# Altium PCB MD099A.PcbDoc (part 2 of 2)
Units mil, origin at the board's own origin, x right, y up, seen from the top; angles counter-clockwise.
Board outline 4255 x 2850 mil, 4 copper layers (Top Layer, Ground, Power, Bottom Layer), stack 61.6 mil thick; 151 components, 81 nets, 392 pads, 633 vias.
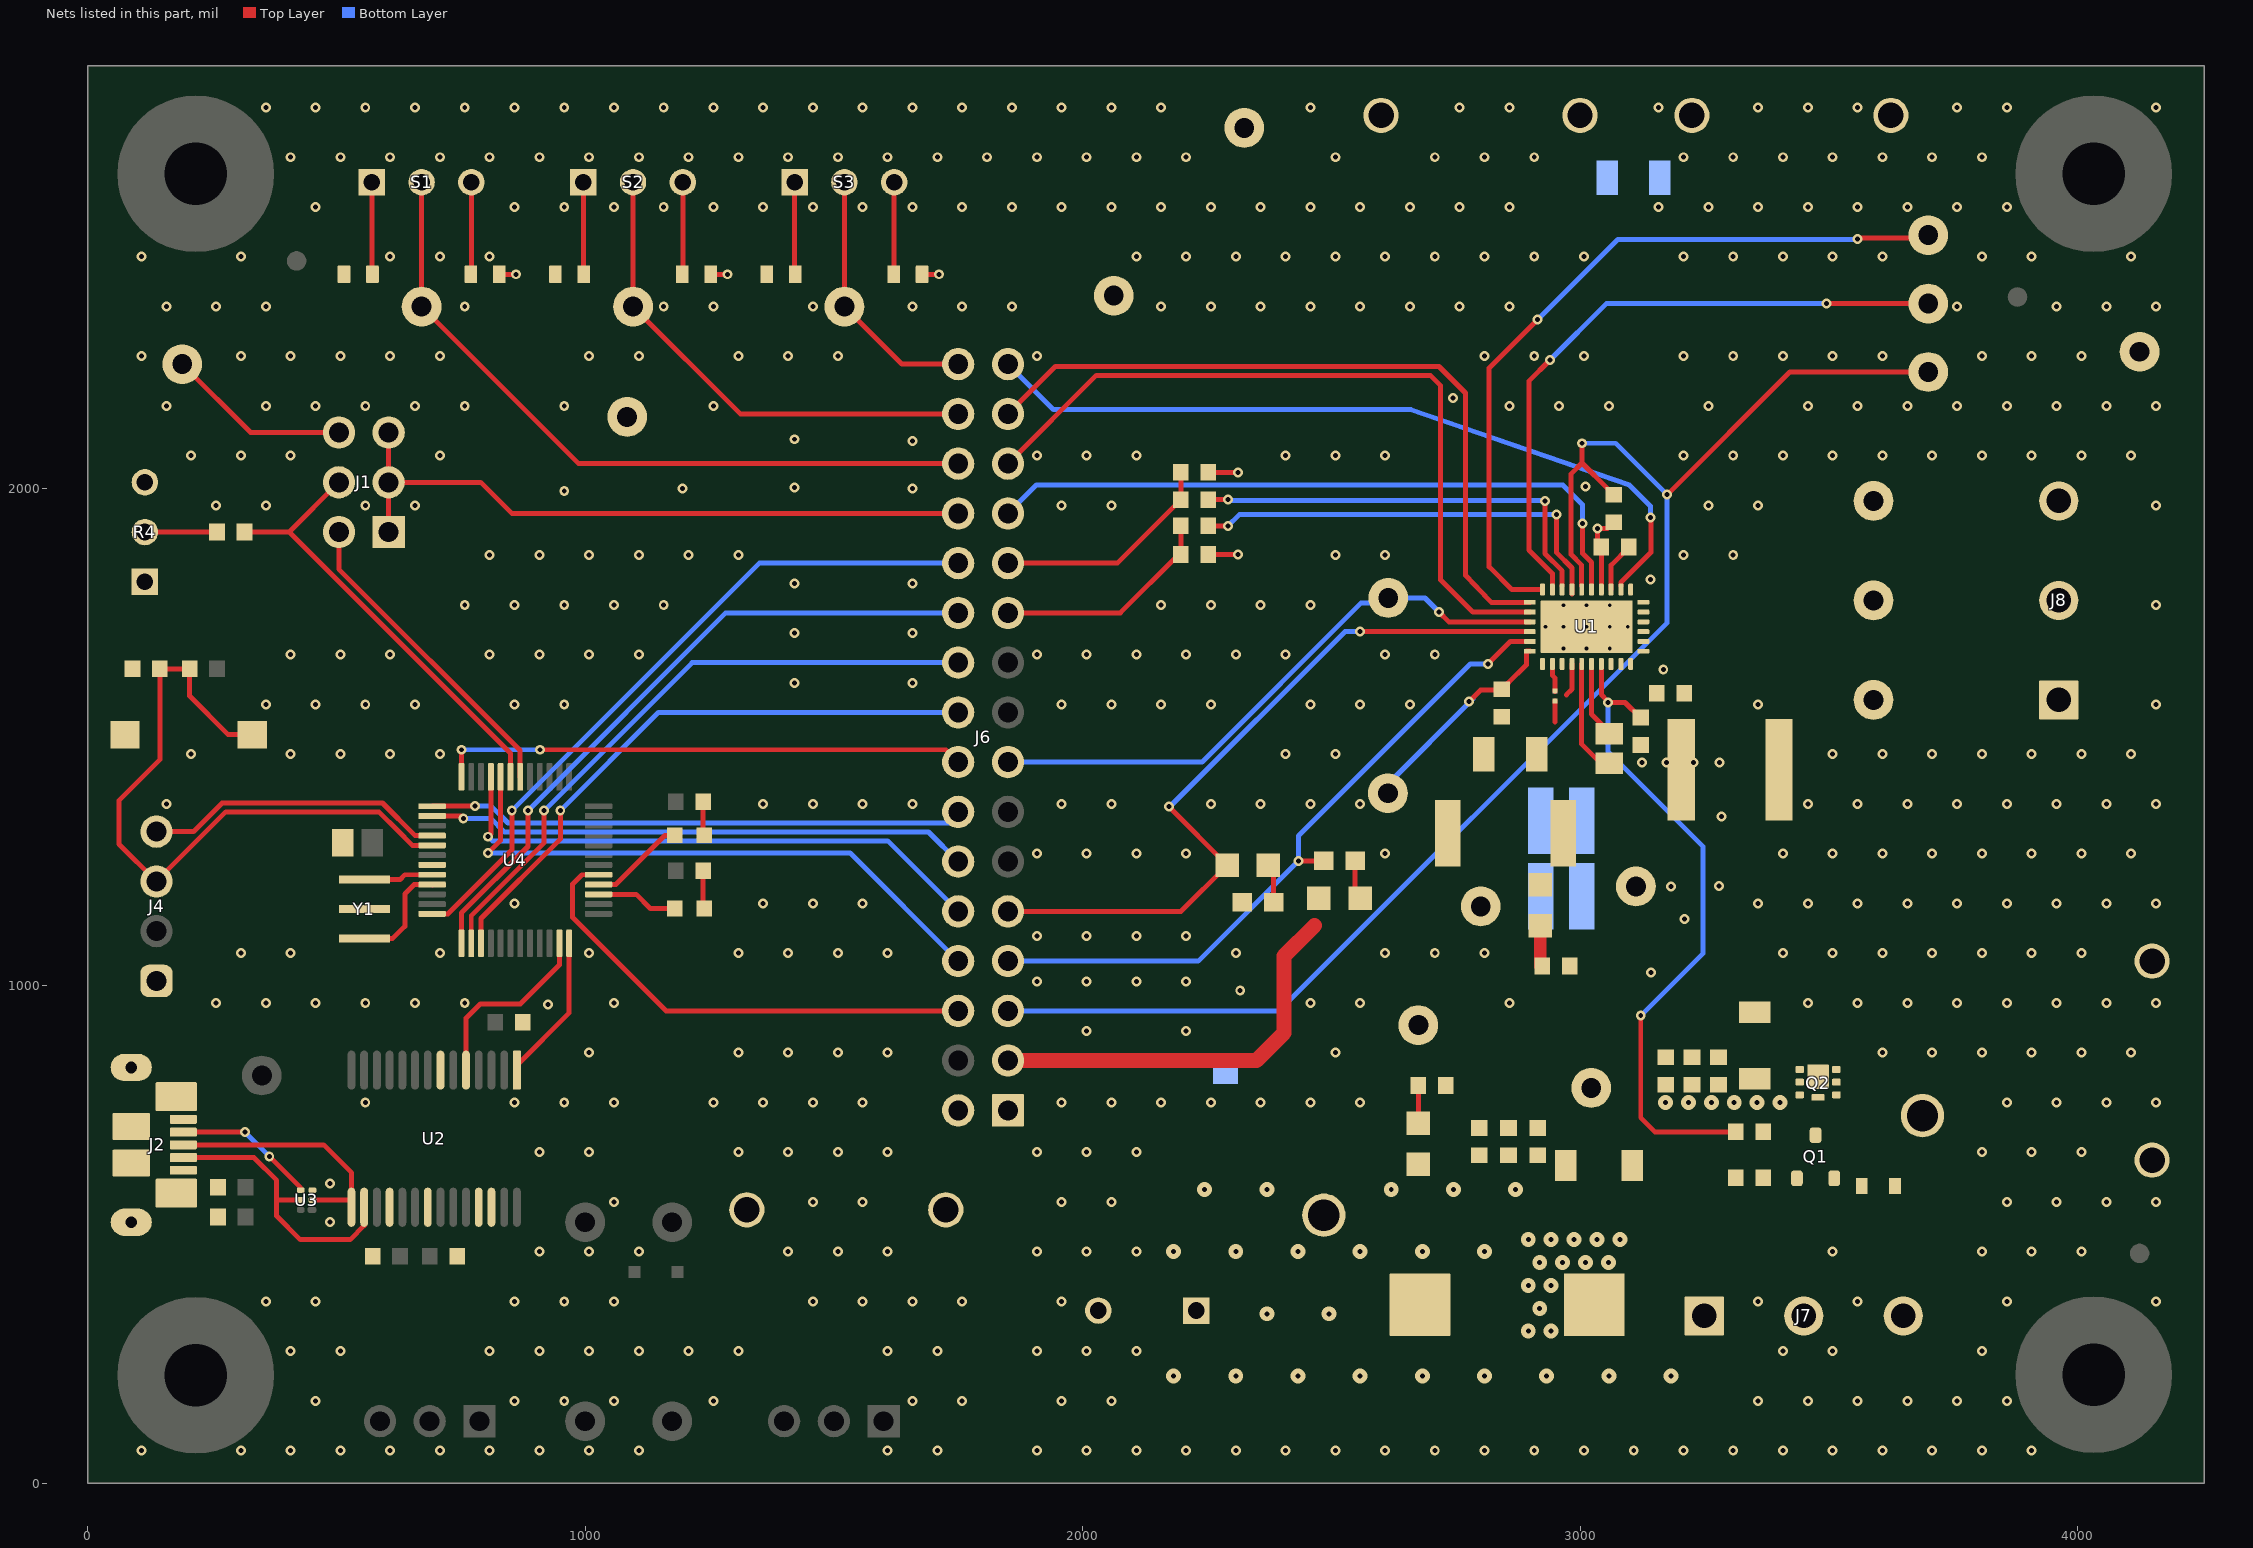
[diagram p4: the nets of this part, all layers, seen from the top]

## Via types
v1: diameter 20, hole 10, Top Layer to Bottom Layer, tented both sides, 580 vias
v2: diameter 30, hole 10, Top Layer to Bottom Layer, tented both sides, 42 vias
v3: diameter 19.68, hole 7.87, Top Layer to Bottom Layer, tented both sides, 11 vias

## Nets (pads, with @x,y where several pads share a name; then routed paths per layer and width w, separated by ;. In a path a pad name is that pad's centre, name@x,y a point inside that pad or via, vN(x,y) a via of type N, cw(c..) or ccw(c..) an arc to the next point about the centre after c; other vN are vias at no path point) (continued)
AGND: C4.1 C5.1 C7.2 C8.2 C9.2 C10.1 C11.2 C12.2 C13.2 J2.5 J2.6 J2.7 J2.8 J2.9 J2.10 J2.11 J4.1 J6.1 J6.2 NT2.1 R4.3 R6.1 R7.1 R8.1 R15.1 R17.1 R24.1 S4.2 TP24.1 TP24.2 TP25.1 TP25.2 TP28.1 TP29.1 TP30.1 U1.1 U1.3 U1.19 U1.33 U2.7 U2.18 U2.21 U2.25 U2.26 U3.3 U4.7 Y1.2 | length 100.3
  Top Layer w10: U1.19@3062.5,1796.91 3062.5,1846.08 3097.93,1881.52 C4.1@3097.93,1882.5
  other v1: 108,66 308,66 408,66 508,66 608,66 708,66 808,66 908,66 1008,66 1108,66 1608,66 1708,66 458,166 858,166 958,166 1058,166 1258,166 1658,166 1758,166 408,266 508,266 808,266 908,266 1008,266 1108,266 1208,266 1308,266 1608,266 1708,266 358,366 458,366 858,366 958,366 1058,366 1458,366 1558,366 1658,366 1758,366 908,466 1008,466 1108,466 1408,466 1508,466 1608,466 487.5,525.08 1058,566 1458,566 1558,566 487.5,602.5 908,666 1008,666 1308,666 1408,666 1508,666 1608,666 558,766 858,766 958,766 1058,766 1258,766 1358,766 1458,766 1558,766 1008,866 1308,866 1408,866 1508,866 1608,866 2508,866 2008,909.3 2208,909.3 925,962.5 258,966 358,966 458,966 558,966 658,966 758,966 1058,966 2458,966 2558,966 2858,966 2316.93,990.7 1908,1009.3 2008,1009.3 2108,1009.3 2208,1009.3 308,1066 408,1066 708,1066 1008,1066 1308,1066 1408,1066 1508,1066 1608,1066 2308,1066 2608,1066 2708,1066 2808,1066 1908,1100 2008,1100 2108,1100 2208,1100 858,1166 1358,1166 1458,1166 1558,1166 1908,1266 2008,1266 2108,1266 2208,1266 2608,1266 158,1366 1358,1366 1458,1366 1558,1366 1658,1366 1958,1366 2058,1366 2258,1366 2358,1366 2458,1366 2558,1366 208,1466 408,1466 508,1466 608,1466 708,1466 2408,1466 2508,1466 358,1566 458,1566 558,1566 658,1566 858,1566 958,1566 1958,1566 2058,1566 2158,1566 2258,1566 2458,1566 2558,1566 2658,1566 1421.27,1609.3 1658,1609.3 408,1666 508,1666 608,1666 808,1666 908,1666 1008,1666 1108,1666 1908,1666 2008,1666 2108,1666 2208,1666 2308,1666 2408,1666 2608,1666 2708,1666 1421.27,1709.3 1658,1709.3 758,1766 858,1766 958,1766 1058,1766 1158,1766 2158,1766 2258,1766 2358,1766 2458,1766 1421.27,1809.3 1658,1809.3 808,1866 908,1866 1008,1866 1108,1866 1208,1866 1308,1866 2508,1866 2608,1866 258,1966 358,1966 558,1966 658,1966 1958,1966 2058,1966 958,1995 1195.29,1999.89 1658,1999.89 1421.27,2002.11 3010.81,2004.4 208,2066 308,2066 408,2066 708,2066 1908,2066 2008,2066 2108,2066 2408,2066 2508,2066 2608,2066 1658,2095.09 1421.27,2099.06 158,2166 358,2166 458,2166 558,2166 658,2166 758,2166 958,2166 1258,2166 2858,2166 2958,2166 3058,2166 2745,2181.65 108,2266 308,2266 408,2266 508,2266 608,2266 708,2266 1008,2266 1108,2266 1308,2266 1408,2266 1508,2266 1908,2266 2808,2266 2908,2266 3008,2266 158,2366 258,2366 358,2366 758,2366 1158,2366 1258,2366 1458,2366 1658,2366 1758,2366 1858,2366 2158,2366 2258,2366 2358,2366 2458,2366 2558,2366 2658,2366 2758,2366 2858,2366 108,2466 308,2466 608,2466 708,2466 808,2466 2108,2466 2208,2466 2308,2466 2408,2466 2508,2466 2608,2466 2708,2466 2808,2466 2908,2466 3008,2466 458,2566 858,2566 958,2566 1058,2566 1158,2566 1258,2566 1358,2566 1458,2566 1558,2566 1658,2566 1758,2566 1858,2566 1958,2566 2058,2566 2158,2566 2258,2566 2358,2566 2458,2566 2558,2566 2658,2566 2758,2566 2858,2566 408,2666 508,2666 608,2666 708,2666 808,2666 908,2666 1008,2666 1108,2666 1208,2666 1308,2666 1408,2666 1508,2666 1608,2666 1708,2666 1808,2666 1908,2666 2008,2666 2108,2666 2208,2666 2508,2666 2708,2666 2808,2666 2908,2666 358,2766 458,2766 558,2766 658,2766 758,2766 858,2766 958,2766 1058,2766 1158,2766 1258,2766 1358,2766 1458,2766 1558,2766 1658,2766 1758,2766 1858,2766 1958,2766 2058,2766 2158,2766 2458,2766 2758,2766 2858,2766
  other v3: 2966.83,1678.8 3013.29,1678.8 3059.74,1678.8 2930.61,1722.11 2966.83,1722.11 3013.29,1722.11 3059.74,1722.11 3095.96,1722.11 2966.83,1765.41 3013.29,1765.41 3059.74,1765.41
ALARM: D3.1 J6.9 U1.30 | length 1509.6
  Top Layer w10: J6.9@1850,1150 2197.82,1150 D3.1@2290.82,1243 2173.82,1360 v1(2173.82,1360.66) ; v1(2558,1712.29) U1.30@2892.3,1712.28
  Bottom Layer w10: v1(2173.82,1360.66) 2175.87,1360.66 2527.5,1712.29 v1(2558,1712.29)
AVDD: C4.2 R1.2 R2.2 R3.2 R4.1 R9.2 R10.1 R11.1 TP5.1 U1.20 | length 355.8
  Top Layer w10: R1.2@826.33,2430.7 v1(861.27,2430.7) ; R2.2@1251.33,2430.7 v1(1286.27,2430.7) ; R3.2@1676.33,2430.7 v1(1711.27,2430.7) ; R11.1@2256.5,1867.5 v1(2312.5,1867.5) ; R10.1@2256.5,2032.5 v1(2312.5,2032.5) ; C4.2@3035,1882.5 v1(3035,1920) 3055.06,1920 R9.2@3067.5,1932.44 ; U1.20@3042.74,1803.72 C4.2@3042.82,1867.53
BRAKE: J6.27 U1.28 | length 1548.5
  Top Layer w10: J6.27@1850,2050 2027.5,2227.5 2699.22,2227.5 2720,2206.72 2720,1816.14 2784.51,1751.63 U1.28@2899.11,1751.63
BRAKE_SW: J6.28 S1.2 TP1.1 | length 1459.5
  Top Layer w10: S1.2@671.27,2615.7 TP1.1@671.27,2365.7 986.97,2050 J6.28@1750,2050
CPH: C6.1 U1.6 | length 149
  Top Layer w10: U1.6@3023.13,1647.3 3023.13,1546.55 3052.64,1517.04 C6.1@3059.14,1517.04
CPL: C6.2 U1.5 | length 243.6
  Top Layer w10: U1.5@3003.44,1647.3 3003.44,1486.23 3052.64,1437.04 C6.2@3059.14,1437.04 ; C6.2@3046.75,1454.47 C6.2@3053.25,1454.47
DACOUT: J6.15 TP12.1 U1.29 | length 1205.7
  Top Layer w10: v1(2716.63,1751.63) 2736.31,1731.95 U1.29@2899.11,1731.95
  Bottom Layer w10: J6.15@1850,1450 2239.93,1450 2559.5,1769.57 2604.07,1769.57 TP12.1@2614.5,1780 2688.26,1780 v1(2716.63,1751.63)
DIR: J6.29 U1.27 | length 1500.5
  Top Layer w10: J6.29@1850,2150 1945.37,2245.37 2716.63,2245.37 2769.89,2192.11 2769.89,1825.62 2818.55,1774.34 2818.64,1774.25 2821.57,1771.32 U1.27@2899.11,1771.32
DIR_SW: J6.30 S2.2 TP2.1 | length 993.1
  Top Layer w10: S2.2@1096.27,2615.7 TP2.1@1096.27,2365.7 1311.97,2150 J6.30@1750,2150
DM: J2.2 U2.16 U3.5 | length 585.4
  Top Layer w10: J2.2@192.22,655 334.14,655 380,609.14 380,570 ; U3.5@428.19,569.59 380.41,569.59 380,570 ; U2.16@556.23,569.59 556.23,518.73 527.5,490 427.5,490 380,537.5 380,570
DP: J2.3 U2.15 U3.2 | length 495.3
  Top Layer w10: J2.3@192.22,680.59 474.41,680.59 530.64,624.36 530.64,569.59 U3.2@451.81,569.59
DRVOFF: J6.31 U1.18 | length 1558.7
  Top Layer w10: U1.18@3082.18,1803.72 3082.18,1811.01 3142.5,1871.33 3142.5,1941.06 v1(3141.37,1942.19)
  Bottom Layer w10: J6.31@1850,2250 1938.51,2161.49 1941.44,2158.56 2658.47,2158.56 2660.14,2158.56 3099.26,2006.92 3141.37,1964.81 v1(3141.37,1942.19)
DRVOFF_SW: J6.32 S3.2 TP3.1 | length 526.7
  Top Layer w10: S3.2@1521.27,2615.7 TP3.1@1521.27,2365.7 1636.97,2250 J6.32@1750,2250
DVDD: C5.2 TP6.1 U1.32 | length 440.2
  Top Layer w10: v1(2777.26,1571.69) 2800.1,1594.53 2841.25,1594.53 2841.25,1595.51 2854.95,1609.22 2855.93,1609.22 2892.04,1645.32 2892.04,1665.82 2892.3,1666.08 2892.3,1672.82 2892.38,1672.89 U1.32@2899.11,1672.89
  Bottom Layer w10: TP6.1@2613.86,1387.5 2613.86,1406.1 v1@2784.51,1576.75
EXT_CLK: TP11.1 U1.26 | length 1518.9
  Top Layer w10: v1(2914.66,2339.39) 2817.5,2242.23 2817.5,1842.5 2863.09,1796.91 U1.26@2924.7,1796.91 ; v1(3558,2501.32) 3560.68,2504 3694.75,2504 TP11.1@3700,2509.25
  Bottom Layer w10: v1(2914.66,2339.39) 3076.3,2501.03 3557.71,2501.03 v1(3558,2501.32)
EXT_WD: TP10.1 U1.25 | length 1299.1
  Top Layer w10: v1(2939.66,2258.4) 2897.16,2215.9 2897.16,1876.36 2944.39,1829.13 U1.25@2944.39,1803.72 ; v1(3495.5,2371.75) TP10.1@3700,2371.75
  Bottom Layer w10: v1(2939.66,2258.4) 3053.01,2371.75 v1(3495.5,2371.75)
FB_BUCK: NT1.1 U1.2 | length 57.5
  Top Layer w10: U1.2@2944.39,1647.3 2944.27,1624.41 2949.38,1619.3 NT1.1@2949.39,1591.93
FG: J6.5 R9.1 TP13.1 U1.22 | length 3142.6
  Top Layer w10: 2982.13,1920.52 2982.13,1867.22 3003.44,1845.91 U1.22@3003.44,1803.72 ; 2982.13,1920.53 2982.13,2029.51 3003.84,2051.22 ; v1(3003.84,2091) 3003.84,2051.22 ; R9.1@3067.5,1987.56 3066.52,1987.56 3055.77,1998.31 3055.77,1999.29 3003.84,2051.22 ; v1(3175.06,1987.56) 3421.75,2234.25 TP13.1@3700,2234.25
  Bottom Layer w10: J6.5@1850,950 2395,950 3175.06,1730.06 v1(3175.06,1987.56) 3071.62,2091 v1(3003.84,2091)
ID: J2.4 U3.4 | length 287.3
  Top Layer w10: J2.4@192.22,706.18 v1(316.27,706.18) ; v1(365,657.5) 428.19,594.31 U3.4@428.19,589.28
  Bottom Layer w10: v1(316.27,706.18) 364.95,657.5 v1(365,657.5)
MCX_SCL: J6.23 R10.2 R12.1 | length 456.9
  Top Layer w10: J6.23@1850,1850 2069.94,1850 R12.1@2197.44,1977.5 2197.44,2028.56 R10.2@2193.5,2032.5
MCX_SDA: J6.21 R11.2 R13.1 | length 451.3
  Top Layer w10: J6.21@1850,1750 2076,1750 2193.5,1867.5 2197.44,1871.44 R13.1@2197.44,1925
MSP_A1_P1.1: J6.12 U4.2 | length 1094.7
  Top Layer w10: U4.2@693.3,1341.67 750.24,1341.67 v1(755,1336.91)
  Bottom Layer w10: v1(755,1336.91) 810.31,1336.91 837.6,1309.63 1690.37,1309.63 J6.12@1750,1250
MSP_A2_P1.2: J6.14 U4.1 | length 1070.7
  Top Layer w10: U4.1@693.3,1361.36 v1(778.64,1361.36)
  Bottom Layer w10: v1(778.64,1361.36) 811.14,1361.36 845,1327.5 J6.14@1750,1327.5
MSP_A3_P1.3: J6.16 U4.48 | length 1063.4
  Top Layer w10: U4.48@751.37,1420.41 v1(751.37,1474.85) ; v1(909.45,1474.85) 1725.15,1474.85 J6.16@1750,1450
  Bottom Layer w10: v1(751.37,1474.85) v1(909.45,1474.85)
MSP_ALARM_P3.2: J6.10 U4.45 | length 1130.1
  Top Layer w10: v1(805,1300) 810.43,1305.43 810.43,1419.43 U4.45@811.33,1420.33
  Bottom Layer w10: v1(805,1300) 813.25,1291.75 1608.25,1291.75 J6.10@1750,1150
MSP_CLK_P4.5: J6.20 U4.14 | length 1282.1
  Top Layer w10: U4.14@771.06,1086.75 771.06,1141.3 917.5,1287.74 v1(917.5,1352.5)
  Bottom Layer w10: v1(917.5,1352.5) 1215,1650 J6.20@1750,1650
MSP_FG_P2.1: J6.6 U4.29 | length 978.8
  Top Layer w10: U4.29@1025.98,1223.56 993.56,1223.56 975,1205 975,1137.5 1162.5,950 J6.6@1750,950
MSP_LED0_P2.2: D6.2 U4.28 | length 195.1
  Top Layer w10: U4.28@1025.98,1203.88 1061.68,1203.88 1160.49,1302.7 D6.2@1180.11,1302.7
MSP_LED1_P2.3: D7.2 U4.27 | length 166
  Top Layer w10: U4.27@1025.98,1184.19 1102.5,1184.19 1131.1,1155.59 D7.2@1180.11,1155.59
MSP_nFAULT_P3.3: J6.8 U4.44 | length 1197.4
  Top Layer w10: v1(805,1267.5) 829.63,1292.13 829.63,1418.94 U4.44@830.11,1419.43
  Bottom Layer w10: v1(805,1267.5) 1532.5,1267.5 J6.8@1750,1050
MSP_PWM: J1.2 U4.42 | length 643.1
  Top Layer w10: J1.2@505.01,1912.5 505.01,1837.78 869.48,1473.31 U4.42@869.48,1420.41
MSP_RX_P4.3: U2.5 U4.23 | length 370.2
  Top Layer w10: U2.5@760.96,841.24 760.96,935.49 789.25,963.78 869.75,963.78 948.22,1042.25 U4.23@948.22,1086.75
MSP_SBWTCK: J4.4 U4.4 | length 617.6
  Top Layer w10: J4.4@145.74,1302.3 137.86,1310.18 212.58,1310.18 270.27,1367.87 592.8,1367.87 658.37,1302.3 U4.4@693.3,1302.3
MSP_SBWTDIO/nRST: C12.1 J4.3 R19.1 S4.1 U4.5 | length 1406.7
  Top Layer w10: S4.1@330.96,1505.27 282.5,1505.27 204.94,1582.83 R19.1@204.94,1637.5 C12.1@145.06,1637.5 145.06,1455 62.5,1372.44 62.5,1285.54 137.86,1210.18 277.68,1350 585.35,1350 624.97,1310.37 ; 625.02,1310.37 650.41,1284.98 ; 650.41,1284.94 652.73,1282.62 U4.5@693.3,1282.62
MSP_SCL_P4.7: J6.24 U4.12 | length 1396.5
  Top Layer w10: U4.12@694.21,1145.73 693.3,1144.82 724.03,1144.82 852.5,1273.3 v1(852.5,1352.5)
  Bottom Layer w10: v1(852.5,1352.5) 1350,1850 J6.24@1750,1850
MSP_SDA_P4.6: J6.22 U4.13 | length 1350.7
  Top Layer w10: U4.13@751.37,1086.75 751.37,1146.89 885,1280.52 v1(885,1352.5)
  Bottom Layer w10: v1(885,1352.5) 1282.5,1750 J6.22@1750,1750
MSP_STE_P4.4: J6.18 U4.15 | length 1213.5
  Top Layer w10: U4.15@790.74,1086.75 790.74,1135.71 950,1294.96 v1(950,1352.5)
  Bottom Layer w10: v1(950,1352.5) 1147.5,1550 J6.18@1750,1550
MSP_TX_P4.2: U2.1 U4.24 | length 288.8
  Top Layer w10: U2.1@863.32,841.24 967.91,945.83 U4.24@967.91,1086.75
MSP_XIN_P2.7: U4.8 Y1.1 | length 141.2
  Top Layer w10: Y1.1@556.22,1213.72 627.85,1213.72 637.69,1223.56 U4.8@693.3,1223.56
MSP_XOUT_P2.6: U4.9 Y1.3 | length 221.8
  Top Layer w10: Y1.3@556.83,1095 Y1.3@556.22,1095.61 613.11,1095.61 637.5,1120 637.5,1185 656.38,1203.88 693.3,1203.88 U4.9@693.3,1202.97
NetC15_1: C15.1 C16.1 C17.1 C18.1 L4.1 Q2.1 Q2.2 Q2.5 Q2.6 Q2.7
  other v2: 2896,306 2942,306 2919,352 2896,398 2942,398 2919,444 2965,444 3011,444 3057,444 2896,490 2942,490 2988,490 3034,490 3080,490 3172,766 3218,766 3264,766 3310,766 3356,766 3402,766
NetD1_2: D1.2 R15.2 | length 81.2
  Top Layer w25: R15.2@2920,1040 D1.2@2920,1121.16
NetD2_2: D2.2 R16.2 | length 79.1
  Top Layer w10: R16.2@2548,1251.5 2548,1186.34 D2.2@2557.84,1176.5
NetD3_2: D3.2 R17.2 | length 79.3
  Top Layer w10: D3.2@2373.5,1243 2384,1232.5 R17.2@2384,1168
NetD4_2: D4.2 R18.2 | length 76.2
  Top Layer w10: D4.2@2675,723.84 R18.2@2675,800
NetD6_1: D6.1 R20.1 | length 68.3
  Top Layer w10: R20.1@1237.2,1370.2 1237.2,1304.67 D6.1@1239.17,1302.7
NetD7_1: D7.1 R21.1 | length 76.7
  Top Layer w10: R21.1@1237.2,1231.43 1237.2,1157.56 D7.1@1239.17,1155.59
NetD8_2: D8.2 Q1.2
NetJ1_6: J1.6 TP4.1 | length 372
  Top Layer w10: TP4.1@190,2250 327.5,2112.5 J1.6@505.01,2112.5
NetJ2_1: J2.1 L3.2
NetQ1_1: Q1.1 R23.1
NetQ1_3: Q1.3 Q2.3 R22.2
NetR1_1: R1.1 S1.3 | length 185
  Top Layer w10: R1.1@771.27,2430.7 S1.3@771.27,2615.7
NetR2_1: R2.1 S2.3 | length 185
  Top Layer w10: R2.1@1196.27,2430.7 S2.3@1196.27,2615.7
NetR3_1: R3.1 S3.3 | length 185
  Top Layer w10: R3.1@1621.27,2430.7 S3.3@1621.27,2615.7
NetR4_2: R4.2 R5.2 | length 144.9
  Top Layer w10: R4.2@115,1912.5 R5.2@259.94,1912.5
NetR6_2: R6.2 S1.1 | length 185
  Top Layer w10: S1.1@571.27,2615.7 571.27,2430.76 R6.2@571.33,2430.7
NetR7_2: R7.2 S2.1 | length 185
  Top Layer w10: R7.2@996.27,2430.7 S2.1@996.27,2615.7
NetR8_2: R8.2 S3.1 | length 185
  Top Layer w10: R8.2@1421.27,2430.7 S3.1@1421.27,2615.7
nFAULT: J6.7 R16.1 U1.31 | length 1395.8
  Top Layer w10: v1(2434,1251.5) R16.1@2485,1251.5 ; v1(2814.68,1647.3) 2859.96,1692.58 U1.31@2899.11,1692.58
  Bottom Layer w10: J6.7@1850,1050 2232.5,1050 v1(2434,1251.5) 2434,1301.88 2779.43,1647.3 v1(2814.68,1647.3)
OUTA: J8.1 TP7.1 U1.11 U1.12
OUTB: J8.2 TP8.1 U1.13 U1.14
OUTC: J8.3 TP9.1 U1.15 U1.16
PGND: C2.2 C3.2 C14.2 C15.2 C16.2 C17.2 C18.2 C19.2 C20.2 C21.2 C22.2 J7.2 NT2.2 R18.1 R23.2 R24.2 TP23.1 TP26.1 TP26.2 TP27.1 TP27.2 TP31.1 U1.10 U1.17
  other v1: 1908,66 2008,66 2108,66 2208,66 2308,66 2408,66 2508,66 2608,66 2708,66 2808,66 2908,66 3008,66 3108,66 3208,66 3308,66 3408,66 3508,66 3608,66 3708,66 3808,66 3908,66 1958,166 2058,166 3358,166 3458,166 3558,166 3658,166 3758,166 3858,166 1908,266 2008,266 2108,266 3408,266 3508,266 3808,266 1958,366 3358,366 3558,366 3858,366 4158,366 1908,466 2008,466 2108,466 3508,466 3808,466 3908,466 4008,466 1958,566 2058,566 3858,566 3958,566 4058,566 4158,566 1908,666 2008,666 2108,666 3808,666 3908,666 4008,666 1958,766 2058,766 2158,766 2258,766 2358,766 2458,766 2558,766 3858,766 3958,766 4058,766 4158,766 3608,866 3708,866 3808,866 3908,866 4008,866 4108,866 3458,966 3558,966 3658,966 3758,966 3858,966 3958,966 4058,966 4158,966 3142.5,1027.5 3408,1066 3508,1066 3608,1066 3708,1066 3808,1066 3908,1066 4008,1066 3210,1135 3358,1166 3458,1166 3558,1166 3658,1166 3758,1166 3858,1166 3958,1166 4058,1166 4158,1166 3408,1266 3508,1266 3608,1266 3708,1266 3808,1266 3908,1266 4008,1266 4108,1266 3458,1366 3558,1366 3658,1366 3758,1366 3858,1366 3958,1366 4058,1366 4158,1366 3508,1466 3608,1466 3708,1466 3808,1466 3908,1466 4008,1466 4108,1466 3358,1566 4158,1566 3167.36,1636.1 4158,1766 3141.37,1816.82 3208,1866 3308,1866 3258,1966 3358,1966 4158,1966 3208,2066 3308,2066 3408,2066 3508,2066 3608,2066 3708,2066 3808,2066 3908,2066 4008,2066 4108,2066 3258,2166 3458,2166 3558,2166 3658,2166 3758,2166 3858,2166 3958,2166 4058,2166 4158,2166 3208,2266 3308,2266 3408,2266 3508,2266 3608,2266 3808,2266 3908,2266 4008,2266 3758,2366 3958,2366 4058,2366 4158,2366 3208,2466 3308,2466 3408,2466 3508,2466 3608,2466 3808,2466 3908,2466 4108,2466 3158,2566 3258,2566 3358,2566 3458,2566 3558,2566 3658,2566 3758,2566 3858,2566 3208,2666 3308,2666 3408,2666 3508,2666 3608,2666 3708,2666 3808,2666 3158,2766 3358,2766 3458,2766 3558,2766 3758,2766 3858,2766 4158,2766
POT: J1.4 R5.1 U4.43 | length 907.7
  Top Layer w10: R5.1@315.06,1912.5 405.01,1912.5 ; J1.4@505.01,2012.5 405.01,1912.5 ; U4.43@849.8,1420.41 849.8,1467.71 405.01,1912.5
SCL: R12.2 U1.24 | length 863.7
  Top Layer w10: R12.2@2252.56,1977.5 v1(2292.5,1977.5) ; v1(2929.63,1975) 2929.63,1869.17 2964.07,1834.72 U1.24@2964.07,1803.72
  Bottom Layer w10: v1(2292.5,1977.5) 2293.75,1976.25 2928.38,1976.25 v1(2929.63,1975)
SDA: R13.2 U1.23 | length 881.6
  Top Layer w10: R13.2@2252.56,1925 v1(2292.5,1925) ; v1(2952.5,1947.5) 2952.5,1871.57 2983.76,1840.31 U1.23@2983.76,1788.13
  Bottom Layer w10: v1(2292.5,1925) 2315,1947.5 v1(2952.5,1947.5)
SPEED: J6.25 U1.21 | length 1366.3
  Top Layer w10: v1(3005,1930) 3005,1869.63 3023.05,1851.58 U1.21@3023.05,1803.72
  Bottom Layer w10: J6.25@1850,1950 1907.09,2007.09 2965.41,2007.09 3005,1967.5 v1(3005,1930)
SPEED_IN: J1.1 J1.3 J1.5 J6.26 | length 1370.9
  Top Layer w10: J1.1@605.01,1912.5 J1.3@605.01,2012.5 ; J1.5@605.01,2112.5 J1.3@605.01,2012.5 ; J6.26@1750,1950 852.5,1950 790,2012.5 J1.3@605.01,2012.5
SW_BUCK: L1.1 L2.1 R14.1 TP14.1 U1.4 | length 66.7
  Top Layer w10: 2972.5,1585.3 2983.76,1596.56 U1.4@2983.76,1647.3
VBAT: D8.1 J7.3 Q2.4 Q2.8 TP21.1
VBK: C7.1 D1.1 D2.1 J6.3 L1.2 L2.2 NT1.2 R14.2 TP15.1 | length 861.4
  Top Layer w10: 2949.38,1530.82 NT1.2@2949.39,1573.2
  Top Layer w30: J6.3@1850,850 2349.7,850 2405,905.3 2405,1060.07 2466.09,1121.16
VCP: C1.1 R22.1 U1.7 | length 1330.6
  Top Layer w10: U1.7@3042.82,1647.3 3042.82,1585.81 3055.94,1572.68 v1(3055.94,1569.98) 3090.49,1569.98 3120.92,1539.55 C1.1@3121.91,1539.55 ; v1(3122.11,940.29) 3122.11,735.08 3150.55,706.64 R22.1@3313.4,706.64
  Bottom Layer w10: v1(3055.94,1569.98) 3055.94,1471.56 3247.5,1280 3247.5,1065.68 v1(3122.11,940.29)
VM: C1.2 C2.1 C3.1 C14.1 C19.1 C20.1 C21.1 C22.1 D4.1 J7.1 L4.2 TP22.1 U1.8 U1.9
  other v1: 3183,1200 3279.84,1201 3284.26,1340.86 3124.28,1449.51 3174.07,1449.51 3228.22,1449.51 3280.49,1449.51
  other v2: 2183,216 2308,216 2433,216 2558,216 2683,216 2808,216 2933,216 3058,216 3183,216 2370.5,341 2495.5,341 2183,466 2308,466 2433,466 2558,466 2683,466 2808,466 2245.5,591 2370.5,591 2620.5,591 2745.5,591 2870.5,591
pads on no net: FID1.1 FID2.1 FID3.1 H1.1 H2.1 H3.1 H4.1 H5.0 H6.0 H7.0 H8.0 J6.4 J6.11 J6.13 J6.17 J6.19 LBL1.0 SH-J1.0 SH-J2.0 SH-J3.0 SH-J4.0 SH-J5.0 SH-J6.0 SH-J7.0 SH-J8.0 SH-J9.0 SH-J10.0 SH-J11.0 SH-J12.0 SH-J13.0 SH-J14.0 SH-J15.0 SH-J16.0 SH-J17.0 SH-J18.0 SH-J19.0 U2.2 U2.3 U2.6 U2.8 U2.9 U2.10 U2.11 U2.12 U2.13 U2.14 U2.19 U2.22 U2.23 U2.24 U2.27 U2.28 U3.1 U4.3 U4.10 U4.11 U4.16 U4.17 U4.18 U4.19 U4.20 U4.21 U4.22 U4.25 U4.26 U4.30 U4.31 U4.32 U4.33 U4.34 U4.35 U4.36 U4.37 U4.38 U4.39 U4.40 U4.41 U4.46 U4.47

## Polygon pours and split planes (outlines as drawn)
AGND on Top Layer "TOP_LAYER_AGND_P247" (solid, remove dead copper, pour order 247): 3146.51,832.5 1800,832.5 1800,0 0,0 0,2850 3146.51,2850
PGND on Top Layer "TOP_LAYER_PGND_P245" (solid, remove dead copper, pour order 245): 1800,0 4255,0 4255,2850 3091.82,2850 3091.82,2165.35 3154.55,2165.35 3154.55,1874.6 3091.82,1827.32 3091.82,1635.21 3313.4,1434.78 3313.4,1168 3091.82,1168 3091.82,832.5 1800,832.5
VM on Top Layer "TOP_LAYER_VM_P233" (solid, remove dead copper, pour order 233): 3088.88,1664.56 3088.88,1616.99 3185.45,1616.99 3185.45,1560.8 3303.21,1560.8 3303.21,1168 3098.21,1168 3098.21,1507.12 3050,1586.99 3050,1664.56
OUTC on Top Layer "TOP_LAYER_OUTC_P243" (solid, remove dead copper, pour order 243): 3113.78,1745.77 3328.28,1745.77 3641.73,1866.76 4112.5,1866.76 4112.5,2046.99 4075,2046.99 3538.61,2046.99 3269.42,1777.8 3113.78,1777.8
OUTB on Top Layer "TOP_LAYER_OUTB_P241" (solid, remove dead copper, pour order 241): 3311.43,1738.18 3621.84,1859.49 4112.5,1859.49 4112.5,1699.49 3418.8,1699.49 3386.64,1705.55 3107.58,1705.55 3107.58,1738.18
OUTA on Top Layer "TOP_LAYER_OUTA_P239" (solid, remove dead copper, pour order 239): 3110,1700.19 3284.84,1700.19 4112.5,1700.19 4112.5,1494.49 3470,1494.49 3299.52,1664.97 3110,1664.97
5VCC on Top Layer "TOP_LAYER_5VCC_P237" (solid, remove dead copper, pour order 237): 707.79,434.34 603.09,434.34 603.09,481.84 707.79,481.84
VBAT on Top Layer "TOP_LAYER_VBAT_P235" (solid, remove dead copper, pour order 235): 3749.99,249.14 3603.46,249.14 3603.46,639.95 3459.35,639.94 3459.34,843.72 3749.99,843.72
SW_BUCK on Top Layer "TOP_LAYER_SW_BUCK_P231" (solid, remove dead copper, pour order 231): 3157.51,1351.82 3013.29,1489.71 3013.29,1582.77 2963.11,1625.78 2963.11,1150 3157.51,1150
DVDD on Top Layer "TOP_LAYER_DVDD_P229" (solid, remove dead copper, pour order 229): 2899.11,1620.19 2870.5,1596.56 2870.5,1574.5 2870.5,1564.72 2807.5,1564.72 2807.5,1617.3 2855.17,1664.97 2899.11,1664.97
VBK on Top Layer "TOP_LAYER_VBK_P223" (solid, remove dead copper, pour order 223): 2445,1099.95 2445,1205 2575.3,1204.73 2917.18,1516.59 2917.18,1540.89 2955,1540.89 2955,1099.95
VM on Top Layer "TOP_LAYER_VM_P219" (solid, remove dead copper, pour order 219): 3015.96,679.14 2150,679.14 2150,164.14 2888.46,164.14 3308.46,164.14 3308.46,289.14 3308.46,376.64 3198.46,376.64 3198.46,289.14 3015.96,289.14
NetC15_1 on Top Layer "TOP_LAYER_NETC15_1_P217" (solid, remove dead copper, pour order 217): 3107.8,535.39 2852.5,535.39 2852.5,253.93 3107.8,253.93
NetD8_2 on Top Layer "TOP_LAYER_NETD8_2_P213" (solid, remove dead copper, pour order 213): 3595.96,641.64 3487.66,641.64 3485.96,639.94 3485.96,556.64 3595.96,556.64
NetQ1_3 on Top Layer "TOP_LAYER_NETQ1_3_P211" (solid, remove dead copper, pour order 211): 3491.05,639.95 3334.15,639.95 3334.15,728.37 3337.42,731.64 3427.95,731.64 3427.95,792.97 3455.52,792.97 3455.52,733.23 3453.93,731.64 3491.05,731.64
NetC15_1 on Top Layer "TOP_LAYER_NETC15_1_P209" (solid, remove dead copper, pour order 209): 3528.88,791.21 3424.06,791.21 3424.06,735.79 3424.89,734.96 3424.89,724.14 3133.88,724.14 3133.46,723.73 3133.46,819.14 3303.21,819.14 3303.46,819.39 3303.46,854.14 3528.88,854.14
NetQ1_1 on Top Layer "TOP_LAYER_NETQ1_1_P207" (solid, remove dead copper, pour order 207): 3485.96,556.64 3340.96,556.64 3340.96,639.94 3485.96,639.94
NetJ2_1 on Top Layer "TOP_LAYER_NETJ2_1_P205" (solid, remove dead copper, pour order 205): 327.14,563.32 176.94,563.32 177.14,645.59 327.14,645.59
5V_USB on Top Layer "TOP_LAYER_5V_USB_P203" (solid, remove dead copper, pour order 203): 374.78,613.98 299.11,613.98 299.11,508.2 374.78,508.2
VM on Power "POWER_VM_P253" (solid, remove dead copper, pour order 253): 2150,200 3300,200 3300,1475 3050,1475 3050,1125 2600,675 2150,675
AGND on Power "POWER_AGND_P263" (solid, remove dead copper, pour order 263): 0,2850 4255,2850 4255,0 0,0
AVDD on Power "POWER_AVDD_P261" (solid, remove dead copper, pour order 261): 2052.5,2470 2125,2397.5 2125,2275 2425,1975 3075,1975 3075,1887.5 2412.5,1887.5 2350,1825 2275,1825 2275,2000 1880,2395 1000,2395 900,2295 900,2000 675,1775 75,1775 75,1850 625,1850 825,2050 825,2420.3 874.7,2470 1930,2470
3V3_MCU on Power "POWER_3V3_MCU_P259" (solid, remove dead copper, pour order 259): 1225,1182.5 1225,537.5 1550,212.5 1550,52.5 1450,52.5 1450,162.5 1125.19,487.31 1125,1125 1075,1175 1057.5,1192.5 372.5,1192.5 235,1055 52.5,1055 52.5,1162.5 200,1162.5 257.5,1220 257.5,1657.5 337.5,1657.5 337.5,1340 1075,1340 1075,1400 1200,1400 1200,1207.5
5V_USB on Power "POWER_5V_USB_P251" (solid, remove dead copper, pour order 251): 437.5,622.5 302.5,622.5 302.5,492.5 437.5,492.5
SW_BUCK on Bottom Layer "BOTTOM_LAYER_SW_BUCK_P269" (solid, remove dead copper, pour order 269): 3042.02,1595.02 3053.64,1459.23 3175,1338.08 3175,1100 2960,1100 2960,1513
PGND on Bottom Layer "BOTTOM_LAYER_PGND_P273" (solid, remove dead copper, pour order 273): 1800,0 1800,832.5 3110,832.5 3110,2850 4255,2850 4255,0
AGND on Bottom Layer "BOTTOM_LAYER_AGND_P281" (solid, remove dead copper, pour order 281): 1800,0 1800,832.5 3110,832.5 3110,2850 0,2850 0,0
NetC15_1 on Bottom Layer "BOTTOM_LAYER_NETC15_1_P271" (solid, pour order 271): 3133.72,819.39 3133.46,536.64 2852.13,536.64 2852.13,253.69 3170.74,253.69 3170.74,392.5 3425.96,392.5 3425.96,819.39
VBK on Bottom Layer "BOTTOM_LAYER_VBK_P267" (solid, remove dead copper, pour order 267): 2970.22,1510.8 2750,1290.58 2750,1100 2960,1100
5V_USB on Bottom Layer "BOTTOM_LAYER_5V_USB_P265" (solid, remove dead copper, pour order 265): 290,490 440,490 440,875 290,875
AGND on Ground "GROUND_AGND_P249" (solid, remove dead copper, pour order 249): 0,2850 4255,2850 4255,0 0,0 0,1695

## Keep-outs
Keep-Out Layer:
  text ".Layer_Name" at 577,-858.49 h60

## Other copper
Top Layer:
  text ".Layer_Name" at 577,-858.49 h60
Bottom Layer:
  text ".Layer_Name" at 577,-858.49 h60

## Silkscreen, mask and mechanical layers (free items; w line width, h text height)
Top Overlay:
  lines w8: 1800,0 1800,2850 ; 1825,2622.5 2110,2622.5 ; 1825,2687.5 2110,2687.5 ; 1826.82,2565.19 2110,2565 ; 1885,2505.38 1885,2749.91 ; 1927.5,2705 1912.5,2717.5 ; 1927.5,2730 1912.5,2717.5 ; 1967.5,2717.5 1912.5,2717.5 ; 1995,2505 1995,2750 ; 2025,2717.5 2080,2717.5 ; 2065,2705 2080,2717.5 ; 2065,2730 2080,2717.5 ; 2466.09,1741.69 2466.09,1651.9 2688.26,1651.9 ; 2466.09,1820.63 2466.09,1909.3 2690.6,1909.34 ; 2693.79,1420.76 3005,1420.76 3005,1306.76 ; 3006.4,1306.76 3350.96,1305.4 ; 3463.55,1305.4 3350.96,1305.4 ; 3464.32,1305.4 3464.32,2045.39 2691.93,2045.39 2691.93,1597.7 2691.93,1424.64 2691.93,1000.26 3350,1000 3350.96,1305.4 ; 520,57.5 852.5,57.5 852.5,390 520,390 520,57.5 ; 1332.5,57.5 1332.5,390 1665,390 1665,57.5 1332.5,57.5 ; 1825,2505 2110,2505 2110,2750 1825,2750 1825,2505
  text "Switches" at 1855,2767.5 h30
  text "S" at 1845,2705 h30
  text "3" at 1845.12,2640.08 h30
  text "OFF" at 1900,2640.08 h30
  text "ON" at 2010,2640.08 h30
  text "2" at 1845,2577.58 h30
  text "ABC" at 1900,2577.58 h30
  text "ACB" at 2012.5,2577.58 h30
  text "BRK" at 1900,2520 h30
  text "RUN" at 2012.5,2520 h30
  text "1" at 1850,2517.5 h30
  text "BRAKE" at 621.27,2463.2 h40
  text "DIR" at 1046.27,2463.2 h40
  text "DRVOFF" at 1471.27,2463.2 h40
  text "DRVOFF_SW" at 1407.5,2237.5 h30
  text "DRVOFF" at 1932.5,2235 h30
  text "SPEED_SEL" at 417.5,2188.5 h40
  text "DIR_SW" at 1502.5,2137.5 h30
  text "DIR" at 1932.5,2135 h30
  text "EXT" at 670,2097.5 h30
  text "BRAKE_SW" at 1437.5,2037.5 h30
  text "BRAKE" at 1932.5,2035 h30
  text "POT" at 227.5,2032.5 h30
  text "POT" at 670,1995 h30
  text "C" at 3662.5,1955 h40
  text "C" at 4175,1955 h40
  text "SPEED_IN" at 1440,1937.5 h30
  text "SPEED" at 1932.5,1935 h30
  text "PWM" at 670,1897.5 h30
  text "MSP_SOMI/SCL" at 1322.5,1837.5 h30
  text "SCL" at 1932.5,1837.44 h30
  text "DACOUT" at 2306.41,1760.01 h40
  text "B" at 3662.5,1755 h40
  text "B" at 4175,1755 h40
  text "MSP_SIMO/SDA" at 1322.5,1737.5 h30
  text "SDA" at 1932.5,1737.69 h30
  text "MSP_CLK" at 1467.5,1637.5 h30
  text "NC" at 1932.5,1637.5 h30
  text "'.DEVICE_NAME'" at 3441.65,1635.83 h60 r90
  text "A" at 3662.5,1555 h40
  text "A" at 4175,1555 h40
  text "MSP_STE" at 1467.5,1537.5 h30
  text "NC" at 1932.5,1535 h30
  text "RST" at 390,1527.5 h30
  text "MSP_A3" at 1497.5,1437.5 h30
  text "DACOUT" at 1932.5,1435 h30
  text "22-ohm" at 2769.89,1380.92 h30
  text "MSP_A2" at 1497.5,1337.5 h30
  text "NC" at 1932.5,1335 h30
  text "'.EVM_Orderable'" at 3499.08,1328.36 h50
  text "SBWTCK" at 225,1296.06 h30
  text "'.PCB_Rev'" at 3498.47,1264.64 h40
  text "MSP_A1" at 1507.5,1237.5 h30
  text "NC" at 1932.5,1235 h30
  text "'.PRJ_Number'-'.VARIANT_NAME'" at 3498.47,1206.25 h30
  text "SBWTDIO" at 225,1197.5 h30
  text "MSP_ALARM" at 1407.5,1137.5 h30
  text "ALARM" at 1932.5,1135 h30
  text "3.3V" at 225,1095 h30
  text "nFAULT" at 2406.66,1076.5 h40
  text "ALARM" at 2184.04,1073.6 h40
  text "MSP_nFAULT" at 1377.5,1037.5 h30
  text "nFAULT" at 1932.5,1035 h30
  text "Buck Reg." at 3326.12,1013.43 h34 r90
  text "GND" at 225,997.5 h30
  text "MSP_FGOUT" at 1407.5,937.5 h30
  text "FGOUT" at 1932.5,935 h30
  text "NC" at 1617.5,835 h30
  text "VBK" at 1932.5,835 h30
  text "AGND" at 1557.5,737.5 h30
  text "PGND" at 1932.5,735 h30
  text "3V3COM" at 1015,600 h30 r90
  text "3V3_MCU" at 1187.5,600 h30 r90
  text "5V_USB" at 600,197.5 h30 r90
  text "5V_EXT" at 800,197.5 h30 r90
  text "5V_EXT" at 1012.5,197.5 h30 r90
  text "3V3EXT" at 1190,197.5 h30 r90
  text "3V3COM" at 1415,197.5 h30 r90
  text "3V3EXT" at 1615,197.5 h30 r90
  text "5V_SEL" at 497.5,110 h40 r90
  text "Connect to VM to bypass" at 2360,105 h35
  text "3V3_SEL" at 1722.5,97.5 h40 r90
  text "VM" at 3217.5,72.5 h40
  text "PGND" at 3370,72.5 h40
  text "VBAT" at 3580,72.5 h40
  text "reverse polarity protection" at 2240,55 h35
  text ".Layer_Name" at 577,-858.49 h30
Bottom Overlay:
  lines w8: 2747.5,1050 3175,1050 3175,1455 2747.5,1455 2747.5,1050
  text "C" at 3690,1955 h40
  text "C" at 4075,1955 h40
  text "B" at 3690,1755 h40
  text "B" at 4075,1755 h40
  text "A" at 3690,1555 h40
  text "A" at 4075,1555 h40
  text "Populate only L1, L2, or" at 3447,1536 h30
  text "R9 (top) for Buck Regulator" at 3447,1478.5 h30
  text "47uH" at 3017.5,1410 h30
  text "Buck Reg." at 3210,1085 h40 r270
  text "22uH" at 3017.5,1067.5 h30
  text "VM" at 3285,220 h40
  text "PGND" at 3517.5,220 h40
  text "VBAT" at 3722.5,220 h40
  text ".Layer_Name" at 577,-858.49 h60
Top Paste:
  text ".Layer_Name" at 577,-858.49 h60
Bottom Paste:
  text ".Layer_Name" at 577,-858.49 h60
Top Solder:
  text ".Layer_Name" at 577,-858.49 h60
  text ".Layer_Name" at 577,-858.49 h60
Bottom Solder:
  text ".Layer_Name" at 577,-858.49 h60
Drill Guide:
  text ".Layer_Name" at 577,-858.49 h60
M1 Board Outline:
  the board outline again, w10
  text ".Layer_Name" at 577,-858.49 h60
M2 Board Dimensions:
  rectangle: 0,-275 125,-150
  rectangle: 125,-400 500,-275
  lines w7: 0,-275 1000,-275 ; 125,-400 125,-150 ; 250,-400 250,-150 ; 500,-400 500,-150 ; 750,-400 750,-150 ; 0,-400 1000,-400 1000,-150 0,-150 0,-400
  text ".Layer_Name" at 577,-858.49 h60
M3 3D STEP Top:
  text ".Layer_Name" at 577,-858.49 h60
M4 3D STEP Bottom:
  text ".Layer_Name" at 577,-858.49 h60
M5 Assembly Top:
  lines w10: -292,-930.17 6308,-930.17 ; -292,-726.83 6310,-726.83 ; -292,-523.5 -292,-1133.5 3713,-1133.5 6310,-1133.5 6310,-523.5 -291.5,-523.5 -291.5,-1133.5 1284,-1133.5 ; 2173,-1133.5 2173,-523.5 ; 3440,-726.83 3440,-523.5 ; 4280,-726.83 4280,-523.5 ; 4902,-1140 4902,-937.17
  text "COMPONENTS MARKED 'DNP' SHOULD NOT BE POPULATED." at 1153.5,-318.5 h60
  text "ASSEMBLY VARIANT:" at 1153,-434 h60
  text ".VariantName" at 2189,-434 h60
  text "PCB VIEWED FROM TOP SIDE" at -228.5,-655.67 h60
  text "BOARD #:" at 2248,-655.67 h60
  text ".PRJ_Number" at 2793.5,-655.67 h60
  text "REV:" at 3638,-655.67 h60
  text ".PCB_Rev" at 3929.5,-655.67 h60
  text "SVN REV:" at 4476,-655.67 h60
  text ".VersionControl_RevNumber" at 4982,-655.67 h60
  text "TID #:" at 2248,-859 h60
  text ".TID" at 2793.5,-859 h60
  text "PLOT NAME =" at -228.5,-1064.34 h60
  text ".plot_File_Name" at 577,-1064.34 h60
  text "GENERATED    :" at 2250,-1064.34 h60
  text ".Print_Date" at 3119.5,-1064.34 h60
  text ".Print_Time" at 3848.5,-1064.34 h60
  text "TEXAS INSTRUMENTS" at 5113,-1064.34 h60
M6 Assembly Bottom:
  lines w10: -292.5,-727.33 6309.5,-727.33 ; -290.5,-930.67 6309.5,-930.67 ; 1115.5,-1140.5 1115.5,-937.67 ; 1737.5,-727.33 1737.5,-524 ; 2577.5,-727.33 2577.5,-524 ; 3844.5,-1134 3844.5,-524 ; 4733.5,-1134 6309,-1134 6309,-524 -292.5,-524 -292.5,-1134 2304.5,-1134 6309.5,-1134 6309.5,-524
  text "COMPONENTS MARKED 'DNP' SHOULD NOT BE POPULATED." at 6102,-318 h60
  text ".VariantName" at 5058,-434 h60
  text "ASSEMBLY VARIANT:" at 6097,-434 h60
  text ".VersionControl_RevNumber" at 1035.5,-656.17 h60
  text "SVN REV:" at 1541.5,-656.17 h60
  text ".PCB_Rev" at 2088,-656.17 h60
  text "REV:" at 2379.5,-656.17 h60
  text ".PRJ_Number" at 3224,-656.17 h60
  text "BOARD #:" at 3769.5,-656.17 h60
  text "PCB VIEWED FROM BOTTOM SIDE" at 6246,-656.17 h60
  text ".TID" at 3224,-859.5 h60
  text "TID #:" at 3769.5,-859.5 h60
  text "TEXAS INSTRUMENTS" at 904.5,-1064.84 h60
  text ".Print_Time" at 2169,-1064.84 h60
  text ".Print_Date" at 2898,-1064.84 h60
  text "GENERATED    :" at 3767.5,-1064.84 h60
  text ".plot_File_Name" at 5440.5,-1064.84 h60
  text "PLOT NAME =" at 6246,-1064.84 h60
M9 Title Sheet:
  drawing of 57 lines, arcs and shapes, not listed
  text "1" at 739.84,8036.5 h70
  text "2" at 3235.5,8036.5 h70
  text "3" at 5724.84,8036.5 h70
  text "4" at 8231.51,8036.5 h70
  text "5" at 10730.5,8036.5 h70
  text "6" at 13235.5,8036.5 h70
  text "A" at -416.5,6893.5 h70
  text "A" at 14383.5,6893.5 h70
  text "B" at -416.5,4513.5 h70
  text "B" at 14383.5,4513.5 h70
  text "C" at -416.5,2138.5 h70
  text "C" at 14383.5,2138.5 h70
  text "PROJECT TITLE:" at 11343.5,277.5 h45
  text ".PRJ_Title" at 11393.5,144.17 h70
  text "DESIGNED FOR:" at 11343.5,-23.5 h45
  text ".PRJ_Customer" at 11393.5,-163.5 h70
  text "D" at -416.5,-231.5 h70
  text "D" at 14383.5,-231.5 h70
  text "FILE NAME:" at 11343.5,-323.5 h45
  text ".PCB_File_Name_No_Path" at 11393.5,-443.5 h70
  text "Texas Instruments (TI) and/or its licensors do not warrant the accuracy or completeness of this specification" at 6374,-605.34 h45
  text "ENGINEER:" at 11343.5,-613.5 h45
  text "LAYOUT BY:" at 12848.5,-613.5 h45
  text "or any information contained therein. TI and/or its licensors do not warrant that this design will meet" at 6329.01,-718 h45
  text ".PRJ_Engineer" at 11393.5,-768.49 h70
  text ".PCB_Layout" at 12899,-768.49 h70
  text "the specifications, will be suitable for your application or fit for any particular purpose, or will operate in" at 6329.01,-830.67 h45
  text ".Layer_Name" at 577,-858.49 h60
  text "ALTIUM DESIGNER VERSION:" at 12848.5,-923.5 h45
  text "an implementation. TI and/or its licensors do not warrant that the design is production worthy. You should" at 6329.01,-943.33 h45
  text "completely validate and test your design implementation to confirm the system functionality for your application." at 6374,-1056 h45
  text ".print_Scale" at 11393.5,-1056.83 h70
  text ".Application_BuildNumber" at 12899,-1056.83 h70
  text "1" at 739.84,-1263.5 h70
  text "2" at 3235.5,-1263.5 h70
  text "3" at 5724.84,-1263.5 h70
  text "4" at 8231.51,-1263.5 h70
  text "5" at 10730.5,-1263.5 h70
  text "6" at 13235.5,-1263.5 h70
M10 Fab Notes:
  drawing of 189 lines, arcs and shapes, not listed
  text "DESIGN INFORMATION" at 12382.02,6356.17 h60
  text "MIN. TRACK WIDTH:" at 11737.46,6224.05 h60
  text "10" at 12833.7,6224.05 h60
  text "MIL" at 12988.46,6224.05 h60
  text "MIN. CLEARANCE:" at 11737.46,6099.92 h60
  text "0.2" at 12773.7,6099.93 h60
  text "mm" at 12988.46,6099.92 h60
  text "MIN. VIA PAD SIZE:" at 11737.46,5975.8 h60
  text "20" at 12803.71,5975.8 h60
  text "MIL" at 12988.46,5975.8 h60
  text "0.05mm (2MIL)" at 12432.46,5845.9 h60
  text "MINIMUM ANNULAR RING" at 11408.23,5837.67 h60
  text "EXTERNAL" at 13140.46,5837.67 h60
  text "PER" at 11608.23,5727.55 h60
  text "IPC-D-275 CLASS 2 LEVEL C" at 11828.23,5727.54 h60
  text "MIL, HOLES" at 13316.46,5627.07 h60
  text "+/-" at 12924,5618.48 h60
  text "+/-" at 13778,5618.48 h60
  text "REGISTRATION TOLERANCES:" at 11408.23,5617.42 h60
  text "METAL" at 12608,5617.42 h60
  text "5" at 13184.2,5617.42 h60
  text "3" at 14017.2,5617.42 h60
  text "MIL" at 14133.46,5617.42 h60
  text "HOLE SIZE TOLERANCE (UNLESS OTHERWISE SPECIFIED):" at 11408.23,5519.1 h60
  text "+/-" at 13778,5516.23 h60
  text "3" at 14017.2,5515.17 h60
  text "MIL" at 14133.46,5515.17 h60
  text "MATERIAL:" at 11333.46,5377.52 h60
  text "FR-4 High Tg" at 12319.9,5249 h60
  text "X" at 12175.46,5241.01 h60
  text "FR-408" at 11754.46,5236.49 h60
  text "OTHER" at 13242.46,5236.49 h60
  text "62 MIL (1.6mm) +/-10%" at 12074.56,5093.46 h60
  text "X" at 11954.46,5091.01 h60
  text "THICKNESS:" at 11408.23,5085.24 h60
  text "OTHER" at 13359.46,5085.24 h60
  text "TOLERANCE:" at 11408.23,4946.92 h60
  text "X" at 12256.46,4946.92 h60
  text "ANSI IPC-6012 TYPE 3 CLASS 2" at 12434.48,4946.92 h60
  text "OTHER +/-" at 12434.46,4802.73 h60
  text "BOW & TWIST:" at 11408.23,4657.54 h60
  text "X" at 12256.46,4657.54 h60
  text "ANSI IPC-6012 TYPE 3 CLASS 2" at 12434.48,4657.54 h60
  text "OTHER +/-" at 12434.46,4510.85 h60
  text "DRILLING:" at 11333.46,4380.23 h60
  text "NC_DRILL FILES" at 13094.46,4275.04 h60
  text "REFERENCE:" at 11408.23,4271.1 h60
  text "X" at 12065.46,4271.01 h60
  text "AS SHOWN" at 12243.46,4271.1 h60
  text "X" at 12966.46,4271.1 h60
  text "OTHER" at 13392.46,4128.85 h60
  text "PTH COPPER THICKNESS:" at 11407.91,4125.32 h60
  text "X" at 12547.14,4125.32 h60
  text "20-30 um" at 12675.14,4125.32 h60
  text "BOARD FINISH:" at 11333.46,3977.73 h60
  text "SILKSCREEN:" at 11488.68,3867.6 h60
  text "X" at 12446.46,3867.6 h60
  text "TOP" at 12563.46,3867.6 h60
  text "X" at 12956.46,3867.6 h60
  text "BOTTOM" at 13074.46,3867.6 h60
  text "SILKSCREEN COLOR:" at 11488.68,3712.41 h60
  text "X" at 12445.46,3712.41 h60
  text "WHITE" at 12563.46,3712.41 h60
  text "OTHER" at 13074.46,3712.41 h60
  text "X" at 12576.46,3568.96 h60
  text "GREEN" at 12694.46,3568.96 h60
  text "OTHER" at 13312.46,3568.96 h60
  text "SOLDER RESIST COLOR:" at 11488.68,3562.1 h60
  text "X" at 12576.46,3414.71 h60
  text "MATTE" at 12694.46,3414.71 h60
  text "SEMI-GLOSS" at 13312,3414.07 h60
  text "IMMERSION GOLD (ENIG)" at 12394.46,3241.94 h60
  text "ENEPIG" at 13732,3234.72 h60
  text "SURFACE FINISH:" at 11333.46,3233.72 h60
  text "X" at 12216.46,3233.72 h60
  text "IMM. TIN/SILVER OR EQUIV" at 11663,3096.4 h60
  text "OTHER" at 13094.46,3092.47 h60
  text "ARRAY/PANEL:" at 11333.46,2937.09 h60
  text "CUT AND TRIM PER M1 BOARD OUTLINE" at 12394.46,2928.87 h60
  text "N.C. ROUTE" at 12394.46,2792.9 h60
  text "X" at 13082.46,2792.9 h60
  text "V. SCORE" at 13260.46,2792.9 h60
  text "CERTIFICATION:" at 11333.46,2663.77 h60
  text "MATERIALS AND WORKMANSHIP FOR ALL PCBS" at 12058.46,2663.77 h60
  text "TO MEET OR EXCEED THE REQUIREMENTS OF:" at 12058.46,2569.71 h60
  text "X" at 11695.97,2441.08 h60
  text "ANSI IPC-A-600F CLASS ->" at 11823.96,2441.08 h60
  text "X" at 13471.97,2441.08 h60
  text "2" at 13581.96,2441.08 h60
  text "1" at 13266.96,2439.58 h60
  text "3" at 13935.96,2439.58 h60
  text "X" at 12507.97,2293.39 h60
  text "RoHS" at 12635.96,2293.39 h60
  text "OTHER" at 13280.36,2293.39 h60
  text "PER ORDER" at 13677.42,2293.39 h60
  text "ALL BOARDS MUST MEET OR EXCEED UL94-V0 REQUIREMENTS." at 11361,2139.57 h60
  text "PCB MUST BEAR THE UL94V-0 UL REGISTERED MATERIAL ID NUMBER" at 11361,2023.5 h60
  text "ADDITIONAL REQUIREMENTS:" at 11333.46,1854.08 h60
  text "MICROSECTION:" at 11408.23,1746.95 h60
  text "YES" at 12313.96,1746.95 h60
  text "REQUIRED" at 13175.46,1602.62 h60
  text "BARE BOARD ELEC. TEST:" at 11408.23,1599.76 h60
  text "NONE" at 12713.96,1599.76 h60
  text "X" at 13057.46,1599.76 h60
  text "PER ORDER" at 13767.46,1599.76 h60
  text "XX MIL VIAS REQUIRE NON-CONDUCTIVE FILL AND PLANARIZE" at 11576.38,1394.82 h59
  text "XX MIL VIAS REQUIRE CONDUCTIVE FILL AND PLANARIZE" at 11584.38,1290.84 h60
  text "OUTER XX MIL TRACES REQUIRE 50 OHM SINGLE-ENDED IMPEDANCE" at 11583.39,1127.46 h58
  text "LAYER 2 & 3 (INNER LAYERS) XX MIL WIDE, XX MIL SPACE / TRACES REQUIRE 100 OHM DIFFERENTIAL IMPEDANCE" at 11575.39,891.74 h60
  text ".Layer_Name" at 577,-858.49 h60
M11 Gerber Information:
  lines w10: -292,-930.17 6308,-930.17 ; -292,-726.83 6310,-726.83 ; -292,-523.5 -292,-1133.5 3713,-1133.5 6310,-1133.5 6310,-523.5 -291.5,-523.5 -291.5,-1133.5 1284,-1133.5 ; 2173,-1133.5 2173,-523.5 ; 3440,-726.83 3440,-523.5 ; 4280,-726.83 4280,-523.5 ; 4902,-1140 4902,-937.17
  text "ALL ARTWORK VIEWED FROM TOP SIDE" at -228.5,-655.67 h60
  text "BOARD #:" at 2248,-655.67 h60
  text ".PRJ_Number" at 2793.5,-655.67 h60
  text "REV:" at 3638,-655.67 h60
  text ".PCB_Rev" at 3929.5,-655.67 h60
  text "SVN REV:" at 4476,-655.67 h60
  text ".VersionControl_RevNumber" at 4982,-655.67 h60
  text "LAYER NAME =" at -228.5,-858.49 h60
  text "TID #:" at 2248,-859 h60
  text ".TID" at 2793.5,-859 h60
  text "PLOT NAME =" at -228.5,-1064.34 h60
  text ".plot_File_Name" at 577,-1064.34 h60
  text "GENERATED    :" at 2250,-1064.34 h60
  text ".Print_Date" at 3119.5,-1064.34 h60
  text ".Print_Time" at 3848.5,-1064.34 h60
  text "TEXAS INSTRUMENTS" at 5113,-1064.34 h60
M12 Stackup:
  drawing of 295 lines, arcs and shapes, not listed
  text "Layer" at 5375,5912.5 h60
  text "Name" at 5784.91,5912.5 h60
  text "Material" at 6714.66,5912.5 h60
  text "Thickness" at 7574.42,5912.5 h60
  text "Constant" at 8224.26,5912.5 h60
  text "Board Layer Stack" at 8794.12,5912.5 h60
  text "Top Overlay" at 5784.91,5792.5 h60
  text "Top Solder" at 5784.91,5672.5 h60
  text "Solder Resist" at 6714.66,5672.5 h60
  text "0.40mil" at 7574.42,5672.5 h60
  text "3.5" at 8224.26,5672.5 h60
  text "1" at 5375,5552.5 h60
  text "Top Layer" at 5784.91,5552.5 h60
  text "1.40mil" at 7574.42,5552.5 h60
  text "Dielectric 1" at 5784.91,5432.5 h60
  text "FR-4" at 6714.66,5432.5 h60
  text "8.00mil" at 7574.42,5432.5 h60
  text "4.2" at 8224.26,5432.5 h60
  text "2" at 5375,5312.5 h60
  text "Ground" at 5784.91,5312.5 h60
  text "1.40mil" at 7574.42,5312.5 h60
  text "Dielectric 2" at 5784.91,5192.5 h60
  text "FR-4" at 6714.66,5192.5 h60
  text "40.00mil" at 7574.42,5192.5 h60
  text "4.2" at 8224.26,5192.5 h60
  text "3" at 5375,5072.5 h60
  text "Power" at 5784.91,5072.5 h60
  text "1.40mil" at 7574.42,5072.5 h60
  text "Dielectric 3" at 5784.91,4952.5 h60
  text "FR-4" at 6714.66,4952.5 h60
  text "8.00mil" at 7574.42,4952.5 h60
  text "4.2" at 8224.26,4952.5 h60
  text "4" at 5375,4832.5 h60
  text "Bottom Layer" at 5784.91,4832.5 h60
  text "1.40mil" at 7574.42,4832.5 h60
  text "Bottom Solder" at 5784.91,4712.5 h60
  text "Solder Resist" at 6714.66,4712.5 h60
  text "0.40mil" at 7574.42,4712.5 h60
  text "3.5" at 8224.26,4712.5 h60
  text "Bottom Overlay" at 5784.91,4592.5 h60
  text ".Layer_Name" at 577,-858.49 h60
M13 Component Bodies Top:
  text ".Layer_Name" at 577,-858.49 h60
M14 Component Bodies Bottom:
  text ".Layer_Name" at 577,-858.49 h60
M15 Courtyards Top:
  text ".Layer_Name" at 577,-858.49 h60
M16 Courtyards Bottom:
  text ".Layer_Name" at 577,-858.49 h60
Drill Drawing:
  circle w10: c5363.63,3542.08 r16.56
  circle w10: c5363.63,3542.08 r27.59
  circle w10: c5363.63,3417.91 r27.59
  lines w10: 5336.04,3045.38 5363.63,3017.78 5391.23,3045.38 5363.63,3072.97 5336.04,3045.38 ; 5336.04,3155.76 5349.83,3155.76 5349.83,3141.96 5377.43,3141.96 5377.43,3155.76 5391.23,3155.76 5391.23,3183.35 5377.43,3183.35 5377.43,3197.15 5349.83,3197.15 5349.83,3183.35 5336.04,3183.35 5336.04,3155.76 ; 5336.04,3266.14 5391.23,3266.14 5391.23,3321.33 5336.04,3321.33 5336.04,3266.14 ; 5336.04,3652.46 5349.83,3652.46 5363.63,3638.66 5377.43,3652.46 5391.23,3652.46 5377.43,3666.26 5391.23,3680.06 5377.43,3680.06 5363.63,3693.85 5349.83,3680.06 5336.04,3680.06 5349.83,3666.26 5336.04,3652.46 ; 5336.04,3818.03 5391.23,3818.03 5363.63,3762.84 5336.04,3818.03 ; 5336.04,3887.02 5363.63,3900.81 5391.23,3887.02 5377.43,3914.61 5391.23,3942.21 5363.63,3928.41 5336.04,3942.21 5349.83,3914.61 5336.04,3887.02 ; 5336.04,4011.19 5391.23,4011.19 5391.23,4066.38 5336.04,4066.38 5336.04,4011.19 ; 5347.07,4022.23 5380.19,4022.23 5380.19,4055.34 5347.07,4055.34 5347.07,4022.23
  lines w12: 5286,2980.53 8515.93,2980.53 ; 5286,4098.12 8515.93,4098.12 ; 5623.73,2856.36 5623.73,4222.29 ; 5955.65,2856.36 5955.65,4222.29 ; 6592.12,2856.36 6592.12,4222.29 ; 6851.18,2856.36 6851.18,4222.29 ; 7226.25,2856.36 7226.25,4222.29 ; 7949.63,2856.36 7949.63,4222.29 ; 5286,2856.36 8515.93,2856.36 8515.93,4222.29 5286,4222.29 5286,2856.36
  text "Symbol" at 5360.51,4135.37 h72
  text "Quantity" at 5660.98,4135.37 h72
  text "Finished Hole Size" at 5992.9,4135.37 h72
  text "Plated" at 6629.38,4135.37 h72
  text "Hole Type" at 6888.43,4135.37 h72
  text "Drill Layer Pair" at 7263.5,4135.37 h72
  text "Hole Tolerance" at 7986.88,4135.37 h72
  text "11" at 5660.98,4011.19 h60
  text "7.87mil (0.200mm)" at 5992.9,4011.19 h60
  text "PTH" at 6629.38,4011.19 h60
  text "Round" at 6888.43,4011.19 h60
  text "Top Layer - Bottom Layer" at 7263.5,4011.19 h60
  text "622" at 5660.98,3887.02 h60
  text "10.00mil (0.254mm)" at 5992.9,3887.02 h60
  text "PTH" at 6629.38,3887.02 h60
  text "Round" at 6888.43,3887.02 h60
  text "Top Layer - Bottom Layer" at 7263.5,3887.02 h60
  text "14" at 5660.98,3762.84 h60
  text "33.47mil (0.850mm)" at 5992.9,3762.84 h60
  text "PTH" at 6629.38,3762.84 h60
  text "Round" at 6888.43,3762.84 h60
  text "Top Layer - Bottom Layer" at 7263.5,3762.84 h60
  text "73" at 5660.98,3638.66 h60
  text "40.00mil (1.016mm)" at 5992.9,3638.66 h60
  text "PTH" at 6629.38,3638.66 h60
  text "Round" at 6888.43,3638.66 h60
  text "Top Layer - Bottom Layer" at 7263.5,3638.66 h60
  text "6" at 5660.98,3514.49 h60
  text "49.21mil (1.250mm)" at 5992.9,3514.49 h60
  text "PTH" at 6629.38,3514.49 h60
  text "Round" at 6888.43,3514.49 h60
  text "Top Layer - Bottom Layer" at 7263.5,3514.49 h60
  text "8" at 5660.98,3390.31 h60
  text "51.18mil (1.300mm)" at 5992.9,3390.31 h60
  text "PTH" at 6629.38,3390.31 h60
  text "Round" at 6888.43,3390.31 h60
  text "Top Layer - Bottom Layer" at 7263.5,3390.31 h60
  text "2" at 5660.98,3266.14 h60
  text "63.00mil (1.600mm)" at 5992.9,3266.14 h60
  text "PTH" at 6629.38,3266.14 h60
  text "Round" at 6888.43,3266.14 h60
  text "Top Layer - Bottom Layer" at 7263.5,3266.14 h60
  text "4" at 5660.98,3141.96 h60
  text "125.98mil (3.200mm)" at 5992.9,3141.96 h60
  text "PTH" at 6629.38,3141.96 h60
  text "Round" at 6888.43,3141.96 h60
  text "Top Layer - Bottom Layer" at 7263.5,3141.96 h60
  text "2" at 5660.98,3017.78 h60
  text "23.62mil (0.600mm)" at 5992.9,3017.78 h60
  text "PTH" at 6629.38,3017.78 h60
  text "Slot" at 6888.43,3017.78 h60
  text "Top Layer - Bottom Layer" at 7263.5,3017.78 h60
  text "742 Total" at 5660.98,2893.61 h60
  text "Slot definitions :" at 5360.51,2806.69 h60
  text "Routed Path Length" at 5810.51,2806.69 h60
  text "= Calculated from tool start centre position to tool end centre position." at 6349.42,2806.69 h60
  text "Hole Length" at 5810.51,2757.02 h60
  text "= Routed Path Length + Tool Size = Slot length as defined in the PCB layout" at 6149.91,2757.02 h60
  text ".Layer_Name" at 577,-858.49 h60
Mechanical 17:
  text ".Layer_Name" at 577,-858.49 h60
Mechanical 18:
  text ".Layer_Name" at 577,-858.49 h60
Mechanical 19:
  text ".Layer_Name" at 577,-858.49 h60

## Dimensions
0,2850 to 4255,0 on M2 Board Dimensions
4255,0 to 0,2850 on M2 Board Dimensions
0,-400 to 1000,-400 on M2 Board Dimensions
